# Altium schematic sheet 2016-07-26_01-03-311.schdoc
size 369 x 220 mm; SheetNumber: 1; SheetTotal: 1
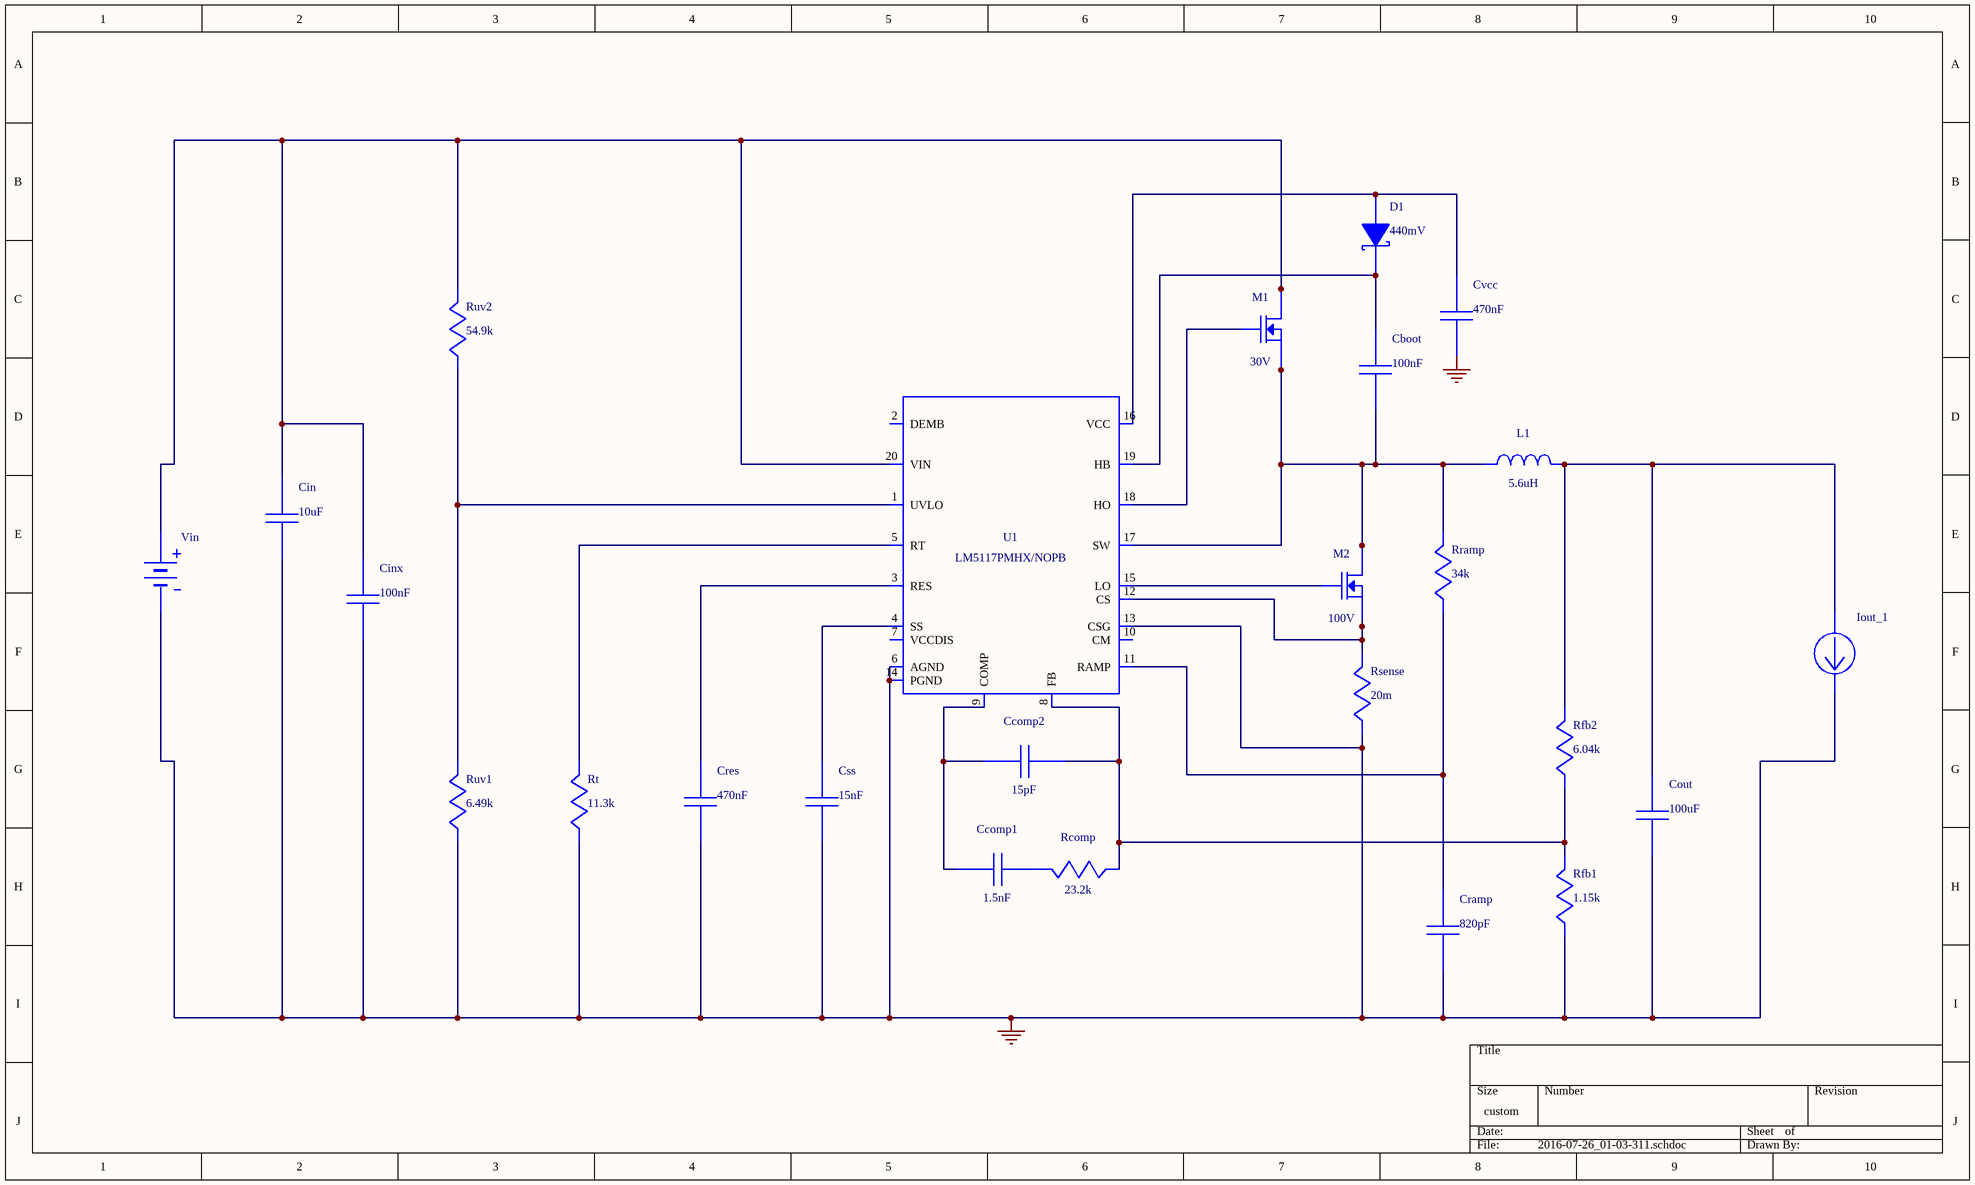
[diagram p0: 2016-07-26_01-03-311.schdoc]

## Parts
Cboot  value 100nF  (hidden comment: GRM155R61A104KA01D)
Ccomp1  value 1.5nF  (hidden comment: CC0805KRX7R9BB152)
Ccomp2  value 15pF  (hidden comment: CC0805JRNPO9BN150)
Cin  value 10uF  (hidden comment: GRM31CR61E106KA12L)
Cinx  value 100nF  (hidden comment: 08053C104KAT2A)
Cout  value 100uF  (hidden comment: GRM31CR60J107ME39L)
Cramp  value 820pF  (hidden comment: CC0805KRX7R9BB821)
Cres  value 470nF  (hidden comment: GRM155C80J474KE19D)
Css  value 15nF  (hidden comment: CC0805KRX7R9BB153)
Cvcc  value 470nF  (hidden comment: GRM155R61A474KE15D)
D1  value 440mV  (hidden comment: CD0603-B0130L)
Iout_1  WB_CURRENT_LOAD  (value not drawn)
L1  value 5.6uH  (hidden comment: SRP6540-5R6M)
M1  value 30V  (hidden comment: CSD17308Q3)
M2  value 100V  (hidden comment: CSD16323Q3)
Rcomp  value 23.2k  (hidden comment: CRCW040223K2FKED)
Rfb1  value 1.15k  (hidden comment: CRCW04021K15FKED)
Rfb2  value 6.04k  (hidden comment: CRCW04026K04FKED)
Rramp  value 34k  (hidden comment: CRCW040234K0FKED)
Rsense  value 20m  (hidden comment: CSR1206FK20L0)
Rt  value 11.3k  (hidden comment: CRCW040211K3FKED)
Ruv1  value 6.49k  (hidden comment: CRCW04026K49FKED)
Ruv2  value 54.9k  (hidden comment: CRCW040254K9FKED)
U1  LM5117PMHX/NOPB
Vin  WB_BATTERY  (value not drawn)

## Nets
0: Cin.2 Cinx.2 Cout.2 Cramp.2 Cres.2 Css.2 Cvcc.2 Iout_1.2(-) Rfb1.2 Rsense.2 Rt.2 Ruv1.2 U1.6(AGND) U1.13(CSG) U1.14(PGND) U1.21(EP) Vin.2(-)
NetCboot_1: Cboot.1 D1.1(K) U1.19(HB)
NetCboot_2: Cboot.2 L1.1 M1.1(Source) M1.2(Source) M1.3(Source) M2.5(Drain) M2.6(Drain) M2.7(Drain) M2.8(Drain) M2.9(Drain) Rramp.1 U1.17(SW)
NetCcomp1_1: Ccomp1.1 Ccomp2.1 U1.9(COMP)
NetCcomp1_2: Ccomp1.2 Rcomp.1
NetCcomp2_2: Ccomp2.2 Rcomp.2 Rfb1.1 Rfb2.2 U1.8(FB)
NetCin_1: Cin.1 Cinx.1 M1.5(Drain) M1.6(Drain) M1.7(Drain) M1.8(Drain) M1.9(Drain) Ruv2.1 U1.20(VIN) Vin.1(+)
NetCout_1: Cout.1 Iout_1.1(+) L1.2 Rfb2.1
NetCramp_1: Cramp.1 Rramp.2 U1.11(RAMP)
NetCres_1: Cres.1 U1.3(RES)
NetCss_1: Css.1 U1.4(SS)
NetCvcc_1: Cvcc.1 D1.2(A) U1.16(VCC)
NetM1_4: M1.4(Gate) U1.18(HO)
NetM2_1: M2.1(Source) M2.2(Source) M2.3(Source) Rsense.1 U1.12(CS)
NetM2_4: M2.4(Gate) U1.15(LO)
NetRt_1: Rt.1 U1.5(RT)
NetRuv1_1: Ruv1.1 Ruv2.2 U1.1(UVLO)

Not connected (* = marked no-connect by the designer): U1 2(DEMB) 7(VCCDIS) 10(CM)

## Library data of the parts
Cboot = GRM155R61A104KA01D: GRM155R61A104KA0; Manufacturer Name: MuRata
Ccomp1 = CC0805KRX7R9BB152: CC0805KRX7R9BB15; Manufacturer Name: Yageo America
Ccomp2 = CC0805JRNPO9BN150: CC0805JRNPO9BN15; Manufacturer Name: Yageo America
Cin = GRM31CR61E106KA12L: GRM31CR61E106KA1; Manufacturer Name: MuRata
Cinx = 08053C104KAT2A: Manufacturer Name: AVX
Cout = GRM31CR60J107ME39L: GRM31CR60J107ME3; Manufacturer Name: MuRata
Cramp = CC0805KRX7R9BB821: CC0805KRX7R9BB82; Manufacturer Name: Yageo America
Cres = GRM155C80J474KE19D: GRM155C80J474KE1; Manufacturer Name: MuRata
Css = CC0805KRX7R9BB153: CC0805KRX7R9BB00; Manufacturer Name: Yageo America
Cvcc = GRM155R61A474KE15D: GRM155R61A474KE1; Manufacturer Name: MuRata
D1 = CD0603-B0130L: Manufacturer Name: Bourns
L1 = SRP6540-5R6M: Unknown; Manufacturer Name: Bourns
M1 = CSD17308Q3: Manufacturer Name: Texas Instruments
M2 = CSD16323Q3: CSD19537Q3; Manufacturer Name: Texas Instruments
Rcomp = CRCW040223K2FKED: Manufacturer Name: Vishay-Dale
Rfb1 = CRCW04021K15FKED: Manufacturer Name: Vishay-Dale
Rfb2 = CRCW04026K04FKED: Manufacturer Name: Vishay-Dale
Rramp = CRCW040234K0FKED: Manufacturer Name: Vishay-Dale
Rsense = CSR1206FK20L0: Manufacturer Name: Stackpole Electronics Inc
Rt = CRCW040211K3FKED: Manufacturer Name: Vishay-Dale
Ruv1 = CRCW04026K49FKED: Manufacturer Name: Vishay-Dale
Ruv2 = CRCW040254K9FKED: Manufacturer Name: Vishay-Dale
U1 = LM5117PMHX/NOPB: Manufacturer Name: Texas Instruments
